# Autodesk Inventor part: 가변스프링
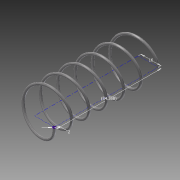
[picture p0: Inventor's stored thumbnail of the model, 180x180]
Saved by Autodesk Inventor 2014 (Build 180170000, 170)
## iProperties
Created: 2016-11
Part Number: 가변스프링
Material: 강철, 탄소
Document SubType Name: Modeling
Designer: NET
Density: 7.87 g/cm^3
Appearance: 반연마
Mass: 14.8385 g
Surface Area: 38.0523 cm^2
Volume: 1.88545 cm^3
Author: NET
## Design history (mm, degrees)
sketch "스케치1"
  geometry: L1 (0, 0)-(16, 0); L2 (16, 0)-(16, 84.368); L3 (16, 84.368)-(0, 84.368); L4 (0, 84.368)-(0, 0); C1 r 1 at (16, 0)
  constraints: 8 end point, 2 parallel, 1 centre point, 1 coincident, 1 horizontal, 1 perpendicular
  dimensions: "d0" = 16 distance of L3.end L2.end; "d1" = 84.36759 distance of L2.end L1.end (derived); "d2" = 2 diameter of C1
feature "코일1" pitch "d3" = 10; turns "d5" = 6; dims "d4" = 84.36759 (= d1), "d6" = 0, angle "d7" = 90 deg, angle "d8" = 90 deg, "d9" = 0, "d10" = 0
node "작업 평면2"
node "작업 평면3"
sketch "스케치4"
  geometry: L1 (15, 0)-(17, 0) reference; 1 further point
  constraints: 1 horizontal alignment
extrude "돌출3" cut sketch "스케치4" distance "d16" = 10; taper "d17" = 0 deg
sketch "스케치5"
  geometry: L1 (17, 0)-(15, 0) reference; 1 further point
  constraints: 1 horizontal alignment
extrude "돌출4" cut sketch "스케치5" distance "d18" = 10; taper "d19" = 0 deg
node "솔리드1"
node "절단 모서리 투영3"
node "절단 모서리 투영4"
